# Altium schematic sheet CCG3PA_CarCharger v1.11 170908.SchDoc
size C
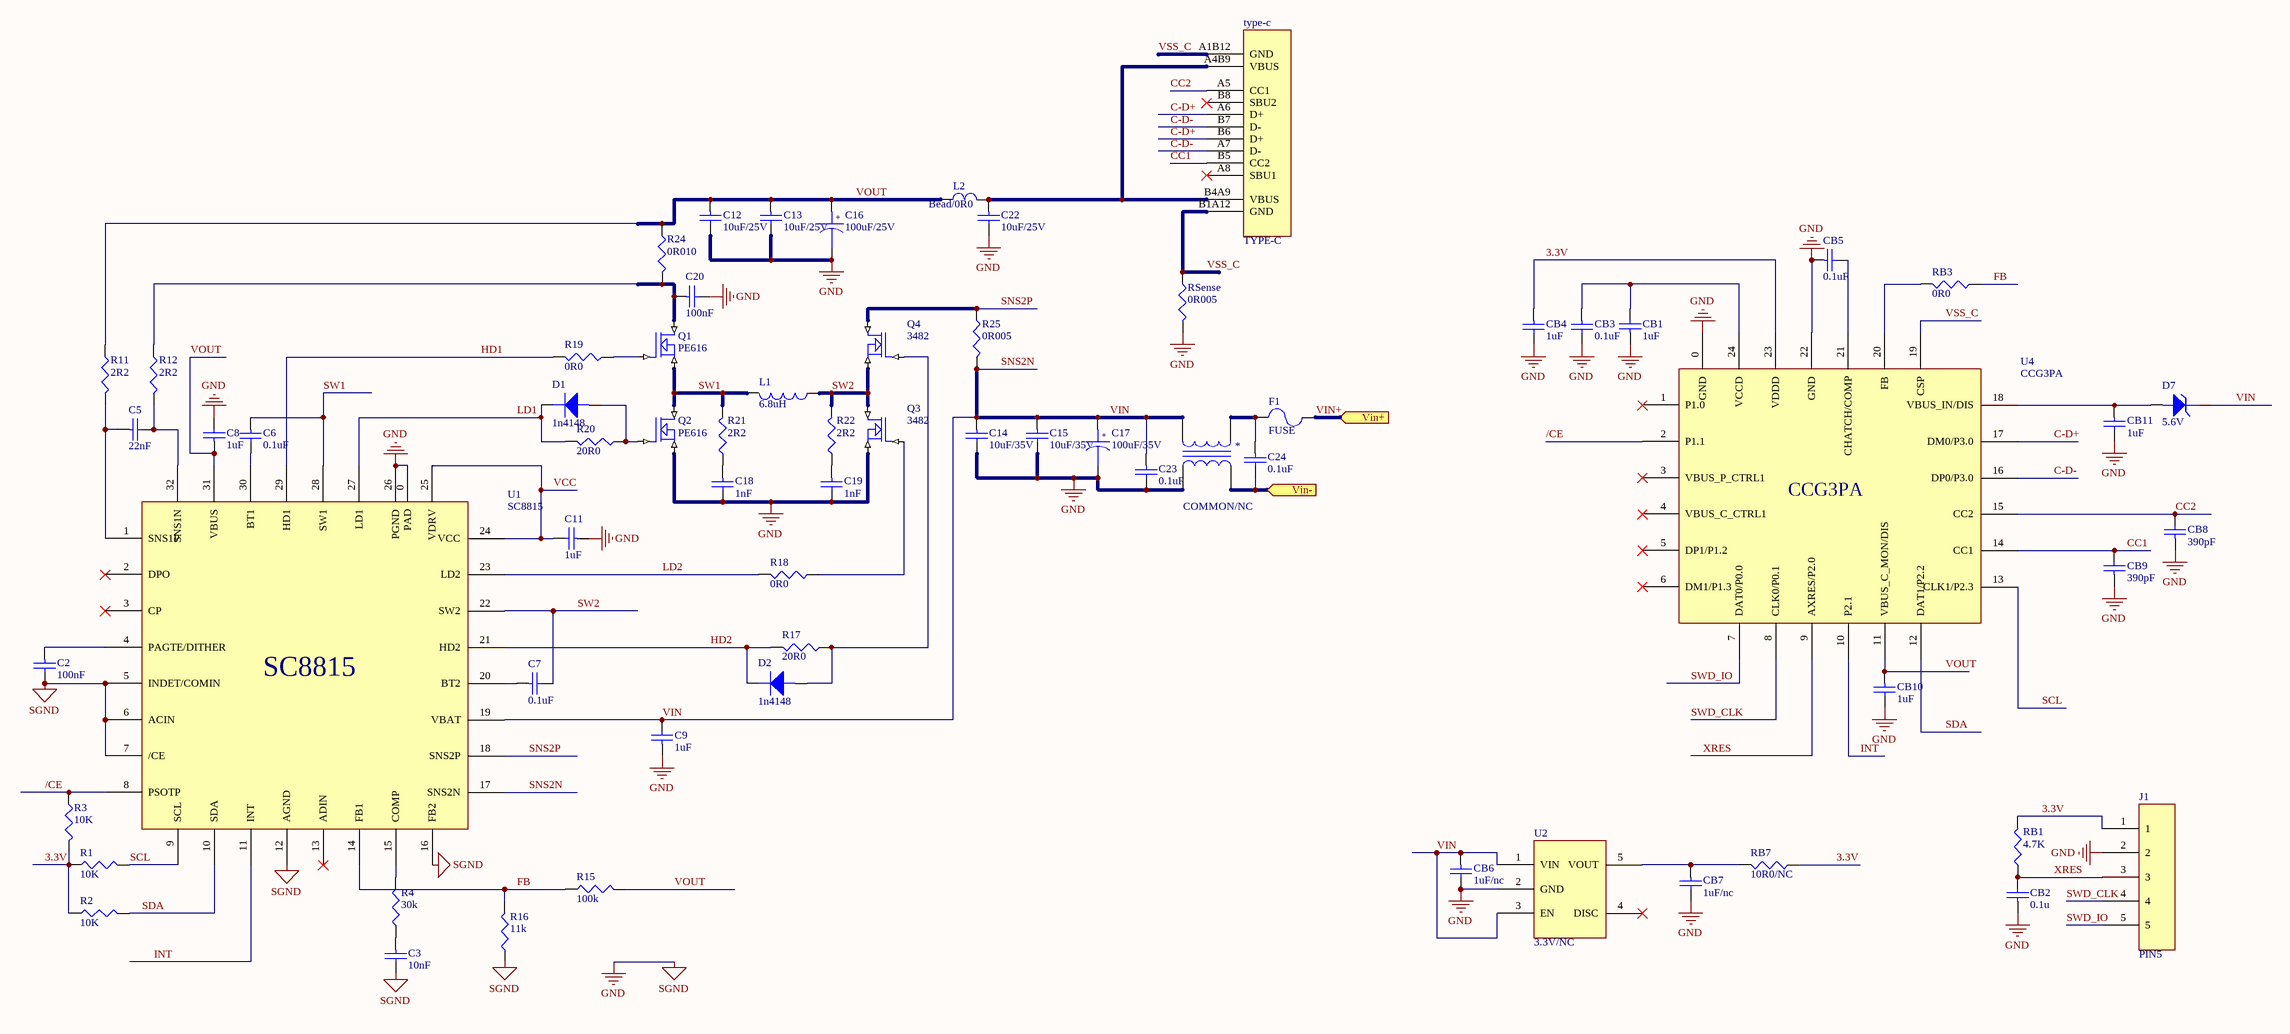
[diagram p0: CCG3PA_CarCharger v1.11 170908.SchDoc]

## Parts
*  COMMON/NC  [Common1]
C2  100nF  [0603]
C3  10nF  [0603]
C5  22nF  [0603]
C6  0.1uF  [0603]
C7  0.1uF  [0603]
C8  1uF  [0603]
C9  1uF  [0603]
C11  1uF  [0603]
C12  10uF/25V  [1206]
C13  10uF/25V  [1206]
C14  10uF/35V  [1206]
C15  10uF/35V  [1206]
C16  100uF/25V  [C4]
C17  100uF/35V  [C4]
C18  1nF  [0603]
C19  1nF  [0603]
C20  100nF  [0805]
C22  10uF/25V  [1206]
C23  0.1uF  [0603]
C24  0.1uF  [0603]
CB1  1uF  [0603]
CB2  0.1u  [0603]
CB3  0.1uF  [0603]
CB4  1uF  [0603]
CB5  0.1uF  [0603]
CB6  1uF/nc  [0603]
CB7  1uF/nc  [0603]
CB8  390pF  [0603]
CB9  390pF  [0603]
CB10  1uF  [0603]
CB11  1uF  [0603]
D1  1n4148  [sod323]
D2  1n4148  [sod323]
D7  5.6V  [D1206]
F1  FUSE  [1206]
J1  PIN5  [pin5]
L1  6.8uH  [L/DB_MPP]
L2  Bead/0R0  [1206]
Q1  PE616  [PDFN-3*3]
Q2  PE616  [PDFN-3*3]
Q3  3482  [PDFN-3*3]
Q4  3482  [PDFN-3*3]
R1  10K  [0603]
R2  10K  [0603]
R3  10K  [0603]
R4  30k  [0603]
R11  2R2  [0603]
R12  2R2  [0603]
R15  100k  [0603]
R16  11k  [0603]
R17  20R0  [0603]
R18  0R0  [0603]
R19  0R0  [0603]
R20  20R0  [0603]
R21  2R2  [0603]
R22  2R2  [0603]
R24  0R010  [1206]
R25  0R005  [1206]
RB1  4.7K  [0603]
RB3  0R0  [0603]
RB7  10R0/NC  [0603]
RSense  0R005  [1206]
type-c  TYPE-C  [type-c3]
U1  SC8815  [TQFN32-4*4L]
U2  3.3V/NC  [SOT-23-5]
U4  CCG3PA  [QFN-24]

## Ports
Vin+ (in), Vin- (in)

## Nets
GND: *.1 C2.2 C3.2 C8.2 C9.1 C11.1 C12.2 C13.2 C14.2 C15.2 C16.2 C17.2 C18.2 C19.2 C20.2 C22.2 C23.2 CB1.1 CB2.1 CB3.2 CB4.2 CB5.1 CB6.2 CB7.2 CB8.1 CB9.1 CB10.2 CB11.2 J1.2 Q2.3(S) Q3.3(S) R16.1 RSense.2 U1.0(PAD) U1.5(INDET/COMIN) U1.6(ACIN) U1.7(/CE) U1.12(AGND) U1.16(FB2) U1.26(PGND) U2.2(GND) U4.0(GND) U4.22(GND)  [also labelled SGND]
3.3V: CB4.1 J1.1 R1.1 R2.1 R3.2 RB1.2 RB7.1 U4.23(VDDD)
/CE: R3.1 U1.8(PSOTP) U4.2(P1.1)
C-D+: type-c.A6(D+) type-c.B6(D+) U4.17(DM0/P3.0)
C-D-: type-c.A7(D-) type-c.B7(D-) U4.16(DP0/P3.0)
CC1: CB9.2 type-c.B5(CC2) U4.14(CC1)
CC2: CB8.2 type-c.A5(CC1) U4.15(CC2)
FB: R15.1 R16.2 RB3.1 U1.14(FB1)
HD1: R19.2 U1.29(HD1)
HD2: D2.2(K) R17.2 U1.21(HD2)
INT: U1.11(INT) U4.10(P2.1)
LD1: D1.2(K) R20.2 U1.27(LD1)
LD2: R18.2 U1.23(LD2)
SCL: R1.2 U1.9(SCL) U4.13(CLK1/P2.3)
SDA: R2.2 U1.10(SDA) U4.12(DAT1/P2.2)
SNS2N: *.3 C9.2 C14.1 C15.1 C17.1 C23.1 CB6.1 D7.2 R25.2 U1.17(SNS2N) U1.19(VBAT) U2.1(VIN) U2.3(EN)  [also labelled VIN]
SNS2P: Q4.2(D) R25.1 U1.18(SNS2P)
SW1: C6.1 L1.2 Q1.3(S) Q2.2(D) R21.2 U1.28(SW1)
SW2: C7.2 L1.1 Q3.2(D) Q4.3(S) R22.2 U1.22(SW2)
SWD_CLK: J1.4 U4.8(CLK0/P0.1)
SWD_IO: J1.5 U4.7(DAT0/P0.0)
VCC: C11.2 U1.24(VCC) U1.25(VDRV)
VIN+: F1.2 ; port Vin+
Vin-: *.2 C24.2 ; port Vin-
VOUT: C8.1 C12.1 C13.1 C16.1 CB10.1 L2.1 R11.1 R15.2 R24.1 U1.31(VBUS) U4.11(VBUS_C_MON/DIS)
VSS_C: RSense.1 type-c.A1B12(GND) type-c.B1A12(GND) U4.19(CSP)
XRES: CB2.2 J1.3 RB1.1 U4.9(AXRES/P2.0)
Net*_4: *.4 C24.1 F1.1
NetC2_1: C2.1 U1.4(PAGTE/DITHER)
NetC3_1: C3.1 R4.1
NetC5_1: C5.1 R11.2 U1.1(SNS1P)
NetC5_2: C5.2 R12.2 U1.32(SNS1N)
NetC6_2: C6.2 U1.30(BT1)
NetC7_1: C7.1 U1.20(BT2)
NetC18_1: C18.1 R21.1
NetC19_1: C19.1 R22.1
NetC20_1: C20.1 Q1.2(D) R12.1 R24.2
NetC22_1: C22.1 L2.2 type-c.A4B9(VBUS) type-c.B4A9(VBUS)
NetCB1_2: CB1.2 CB3.1 U4.24(VCCD)
NetCB5_2: CB5.2 U4.21(CHATCH/COMP)
NetCB7_1: CB7.1 RB7.2 U2.5(VOUT)
NetCB11_1: CB11.1 D7.1 U4.18(VBUS_IN/DIS)
NetD1_1: D1.1(A) Q2.1(G) R20.1
NetD2_1: D2.1(A) Q4.1(G) R17.1
NetQ1_1: Q1.1(G) R19.1
NetQ3_1: Q3.1(G) R18.1
NetR4_2: R4.2 U1.15(COMP)
NetRB3_2: RB3.2 U4.20(FB)

Not connected (* = marked no-connect by the designer): type-c A8(SBU1)* B8(SBU2)*; U1 2(DPO)* 3(CP)* 13(ADIN)*; U2 4(DISC)*; U4 1(P1.0)* 3(VBUS_P_CTRL1)* 4(VBUS_C_CTRL1)* 5(DP1/P1.2)* 6(DM1/P1.3)*

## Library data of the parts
* = COMMON
C2 C3 C5-C9 C11-C15 C18-C20 C22-C24 CB1 CB2 CB6 CB7 = CAP
C16 C17 = CAP2
CB3-CB5 CB8-CB11 = CAP: 精度: 10%
D1 D2 = DIODE 1: DIODE
D7 = ZENER
L1 = L: inductor
L2 = Bead
Q1-Q4 = NMOS
R1-R3 = RES: 精度: 1%
R4 R11 R12 R15-R22 R24 R25 RB1 RB3 RB7 RSense = RES
type-c = type-c1
U2 = GS7138S2: LDO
